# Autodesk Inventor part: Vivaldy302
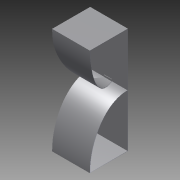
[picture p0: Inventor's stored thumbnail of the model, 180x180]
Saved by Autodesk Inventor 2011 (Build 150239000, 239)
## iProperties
Created: 2014-05
Part Number: Vivaldy302
Document SubType Name: Modeling
Designer: Evgeny
Density: 1 g/cm^3
Author: Evgeny
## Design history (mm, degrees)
sketch "Эскиз1"
  geometry: L1 (-53.5, -1.5)-(53.5, -1.5); L2 (53.5, -1.5)-(53.5, -0.5); L3 (53.5, -0.5)-(-53.5, -0.5); L4 (-53.5, -0.5)-(-53.5, -1.5); 1 further point
  constraints: 8 end point, 2 parallel, 1 horizontal, 1 perpendicular
  dimensions: "d0" = 107 distance between parallel lines of L2 L4; "d1" = 53.5 horizontal distance of L3.end point (0, 0); "d2" = 1 distance between parallel lines of L1 L3; "d9" = 1.5 distance from line of L1 point (0, 0)
sketch "Эскиз2"
  geometry: L1 (-150, 105)-(-150, -2); L2 (-150, -2)-(150, -2); L3 (150, -2)-(150, 105); 5 further points; 2 other entities
  constraints: 6 end point, 2 point on line, 1 parallel, 1 vertical, 8 other
  dimensions: "d5" = 300 distance between parallel lines of L1 L3; "d6" = 150 distance from line of L1 point (0, 0); "d7" = 2 distance from line of L2 point (0, 0)
feature "Сдвиг2" sketch "Эскиз1", "Эскиз2" dims "d10" = 0
sketch "Эскиз3"
  geometry: L1 (0, 1)-(107, 1); L2 (107, 1)-(107, 0); L3 (107, 0)-(0, 0); L4 (0, 0)-(0, 1); 1 further point
  constraints: 8 end point, 2 parallel, 1 horizontal, 1 perpendicular
extrude "Выдавливание1" join sketch "Эскиз3" distance "d11" = 2; taper "d12" = 0 deg
sketch "Эскиз4"
  geometry: L1 (0, -1)-(107, -1); L2 (107, -1)-(107, 5); L3 (107, 5)-(0, 5); L4 (0, 5)-(0, -1); 1 further point
  constraints: 8 end point, 2 parallel, 1 horizontal, 1 perpendicular
extrude "Выдавливание2" join sketch "Эскиз4" distance "d13" = 1; taper "d14" = 0 deg
sketch "Эскиз5"
  geometry: L1 (-10, -1)-(-55, -1); L2 (-55, -1)-(-55, 106); L3 (-55, 106)-(-10, -1); L4 (10, -1)-(55, -1); L5 (55, -1)-(55, 106); L6 (55, 106)-(10, -1); 1 further point
  constraints: 12 end point, 3 perpendicular, 1 horizontal
extrude "Выдавливание3" cut sketch "Эскиз5" distance "d15" = 148; taper "d16" = 0 deg
sketch "Эскиз6"
  geometry: C1 r 0.635 at (-53.5, 2.503); 1 further point
  constraints: 1 centre point
  dimensions: "d17" = 1.27 diameter of C1
extrude "Выдавливание4" cut sketch "Эскиз6" distance "d18" = 2; taper "d19" = 0 deg
sketch "Эскиз7"
  geometry: C1 r 2.125 at (53.5, -145.491); 1 further point
  constraints: 1 centre point
  dimensions: "d20" = 4.25 diameter of C1
extrude "Выдавливание5" cut sketch "Эскиз7" distance "d21" = 2; taper "d22" = 0 deg
node "Твердое тело2"
